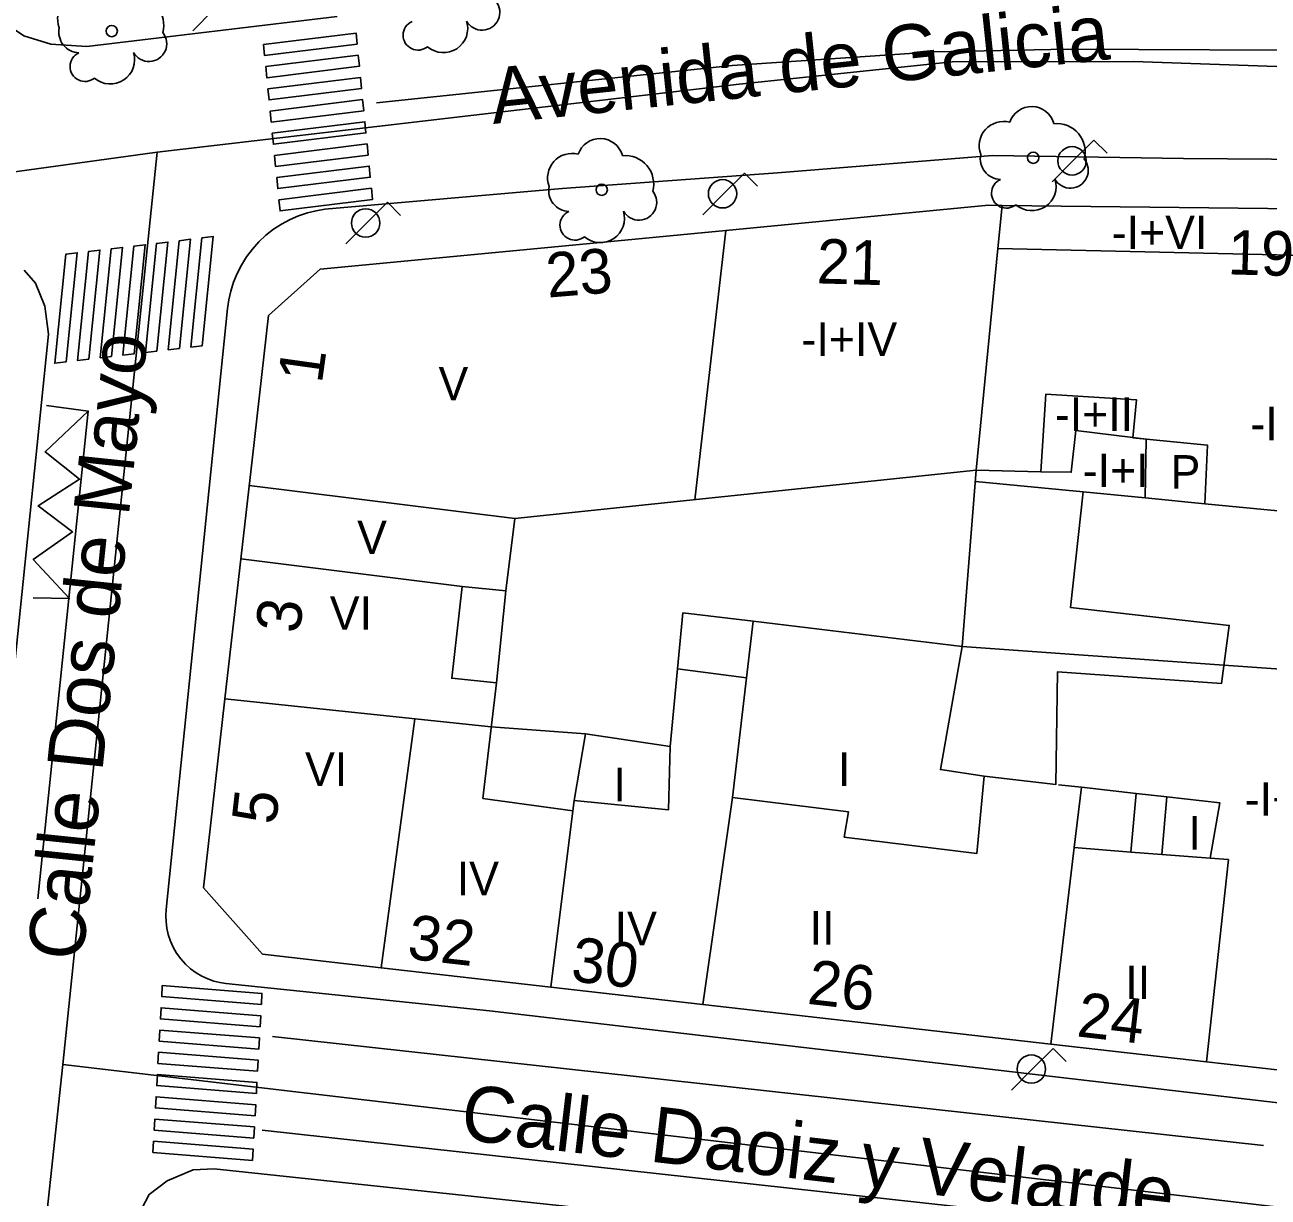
# Model space of a CAD drawing. Extents: x 282771 to 285132, y 4823109 to 4825496.
# Drawn here: x 283049.2 to 283104.9, y 4824300.3 to 4824352.9 of the extents above; entities that cross this region are included whole.
import ezdxf

# ---------------------------------------------------------------- set-up
doc = ezdxf.new("R2010")
doc.units = 0
for name, color, linetype in [('ACERA-BORDILLO', 7, 'Continuous'), ('ARBOL', 7, 'Continuous'), ('CALLE-EJE', 7, 'Continuous'), ('CALLE-TEXTO', 7, 'Continuous'), ('CARGA_DESCARGA', 7, 'Continuous'), ('EDIFICIO', 7, 'Continuous'), ('FAROLA', 7, 'Continuous'), ('INTERIOR-EDIFICIO', 7, 'Continuous'), ('MEDIANERA', 7, 'Continuous'), ('NUM-LOCAL', 7, 'Continuous'), ('NUM-PORTAL', 7, 'Continuous'), ('PASO-PEATONES', 7, 'Continuous'), ('SENAL-VIARIA', 7, 'Continuous'), ('TXT-ALTURA-EDIFICIO', 7, 'Continuous')]:
    doc.layers.add(name, color=color, linetype=linetype)

msp = doc.modelspace()

# ---------------------------------------------------------------- linework, layer by layer
at = {"layer": 'ACERA-BORDILLO'}
for points in [[(283063.163, 4824353.319), (283051.925, 4824351.968), (283050.316, 4824352.068), (283049.108, 4824352.451), (283048.263, 4824353.014)], [(283101.131, 4824346.943), (283092.557, 4824347.075), (283082.908, 4824346.3), (283073.26, 4824345.596), (283062.607, 4824344.665), (283062.217, 4824344.601), (283061.825, 4824344.504), (283061.433, 4824344.373), (283061.046, 4824344.206), (283060.67, 4824344.004), (283060.308, 4824343.768), (283059.966, 4824343.499), (283059.647, 4824343.2), (283059.355, 4824342.875), (283059.094, 4824342.527), (283058.865, 4824342.16), (283058.671, 4824341.78), (283058.513, 4824341.39), (283058.39, 4824340.995), (283058.301, 4824340.601), (283058.245, 4824340.21), (283055.497, 4824313.24), (283055.479, 4824312.969), (283055.486, 4824312.689), (283055.521, 4824312.403), (283055.585, 4824312.114), (283055.679, 4824311.827), (283055.804, 4824311.546), (283055.959, 4824311.277), (283056.142, 4824311.025), (283056.35, 4824310.792), (283056.58, 4824310.584), (283056.828, 4824310.402), (283057.088, 4824310.248), (283057.357, 4824310.124), (283057.629, 4824310.029), (283057.902, 4824309.963), (283058.17, 4824309.923), (283069.988, 4824308.701), (283107.558, 4824304.319)], [(283110.99, 4824346.873), (283101.131, 4824346.943)], [(283049.123, 4824341.934), (283049.628, 4824341.348), (283050.042, 4824340.313), (283050.215, 4824339.059), (283045.739, 4824295.551)], [(283057.649, 4824301.605), (283056.704, 4824301.565), (283055.537, 4824301.062), (283054.732, 4824300.458), (283053.927, 4824298.908)], [(283105.578, 4824296.501), (283057.649, 4824301.605)]]:
    msp.add_lwpolyline(points, dxfattribs=at)
at = {"layer": 'ARBOL'}
for centre in [(283053.048, 4824352.663), (283094.384, 4824346.977), (283075.026, 4824345.543)]:
    msp.add_circle(centre, 0.255, dxfattribs=at)
for centre, radius, start, end in [((283051.718, 4824353.193), 1.097, 75.4318, 200.5561), ((283054.108, 4824352.923), 1.272, 345.0327, 95.7993), ((283069.66, 4824353.498), 0.797, 208.9625, 38.991), ((283066.79, 4824352.478), 0.672, 113.7367, 309.4725), ((283067.93, 4824352.778), 1.086, 228.9545, 17.928), ((283051.608, 4824352.623), 0.935, 168.599, 268.1324), ((283054.718, 4824352.093), 0.797, 208.9625, 38.991), ((283051.848, 4824351.073), 0.672, 113.7367, 309.4725), ((283052.988, 4824351.373), 1.086, 228.9545, 17.928), ((283094.314, 4824348.237), 1.038, 15.6423, 161.3843), ((283093.054, 4824347.507), 1.097, 75.4318, 200.5561), ((283095.444, 4824347.237), 1.272, 345.0327, 95.7993), ((283074.956, 4824346.803), 1.038, 15.6423, 161.3843), ((283073.696, 4824346.073), 1.097, 75.4318, 200.5561), ((283076.086, 4824345.803), 1.272, 345.0327, 95.7992), ((283092.944, 4824346.937), 0.935, 168.599, 268.1324), ((283096.054, 4824346.407), 0.797, 208.9625, 38.991), ((283073.586, 4824345.503), 0.935, 168.599, 268.1324), ((283093.184, 4824345.387), 0.672, 113.7367, 309.4725), ((283094.324, 4824345.687), 1.086, 228.9545, 17.928), ((283076.696, 4824344.973), 0.797, 208.9625, 38.991), ((283073.826, 4824343.953), 0.672, 113.7367, 309.4725), ((283074.966, 4824344.253), 1.086, 228.9545, 17.928)]:
    msp.add_arc(centre, radius, start, end, dxfattribs=at)
at = {"layer": 'CALLE-EJE'}
for points in [[(283119.458, 4824350.58), (283098.878, 4824351.3), (283090.752, 4824351.284), (283081.188, 4824350.281), (283055.088, 4824347.221)], [(283055.088, 4824347.221), (283042.609, 4824345.501)], [(283055.088, 4824347.221), (283050.849, 4824306.281)], [(283045.479, 4824254.042), (283049.709, 4824295.551), (283050.849, 4824306.281)], [(283113.935, 4824298.88), (283050.849, 4824306.281)]]:
    msp.add_lwpolyline(points, dxfattribs=at)
at = {"layer": 'CARGA_DESCARGA'}
msp.add_lwpolyline([(283050.129, 4824335.859), (283051.995, 4824335.612), (283050.059, 4824333.78), (283051.608, 4824332.547), (283049.742, 4824331.35), (283051.291, 4824330.187), (283049.53, 4824328.954), (283051.15, 4824327.193), (283049.53, 4824327.228)], dxfattribs=at)
at = {"layer": 'EDIFICIO'}
msp.add_lwpolyline([(283058.128, 4824322.691), (283059.358, 4824333.541), (283060.078, 4824339.891), (283062.398, 4824341.971), (283072.458, 4824342.931), (283080.598, 4824343.711), (283092.378, 4824344.851), (283092.988, 4824344.841), (283110.208, 4824344.641), (283113.058, 4824341.861), (283111.778, 4824330.521), (283110.988, 4824323.631), (283110.268, 4824317.201), (283109.287, 4824308.473), (283106.126, 4824305.952), (283102.158, 4824306.401), (283095.178, 4824307.201), (283079.558, 4824308.981), (283072.748, 4824309.761), (283065.128, 4824310.631), (283059.808, 4824311.241), (283057.169, 4824314.221), (283058.128, 4824322.691)], dxfattribs=at)
at = {"layer": 'FAROLA'}
for p, q in [((283057.61, 4824353.616), (283056.68, 4824352.676)), ((283097.107, 4824347.769), (283096.167, 4824346.839)), ((283097.697, 4824347.179), (283097.107, 4824347.769)), ((283096.167, 4824346.839), (283095.237, 4824345.899)), ((283081.428, 4824346.29), (283080.488, 4824345.36)), ((283082.018, 4824345.7), (283081.428, 4824346.29)), ((283080.488, 4824345.36), (283079.558, 4824344.42)), ((283065.418, 4824344.978), (283064.478, 4824344.048)), ((283066.008, 4824344.388), (283065.418, 4824344.978)), ((283064.478, 4824344.048), (283063.548, 4824343.108)), ((283095.278, 4824307.011), (283094.338, 4824306.081)), ((283095.868, 4824306.421), (283095.278, 4824307.011)), ((283094.338, 4824306.081), (283093.408, 4824305.141))]:
    msp.add_line(p, q, dxfattribs=at)
for centre in [(283096.127, 4824346.839), (283080.448, 4824345.36), (283064.438, 4824344.048), (283094.298, 4824306.081)]:
    msp.add_circle(centre, 0.637, dxfattribs=at)
at = {"layer": 'INTERIOR-EDIFICIO'}
for points in [[(283091.822, 4824332.951), (283094.728, 4824332.881), (283094.948, 4824336.361), (283099.018, 4824336.111), (283098.847, 4824334.41), (283102.198, 4824334.081), (283102.078, 4824331.451), (283099.408, 4824331.721), (283096.628, 4824331.991), (283096.058, 4824326.791), (283103.178, 4824325.991), (283102.828, 4824323.381), (283095.478, 4824323.911), (283095.405, 4824318.854), (283092.188, 4824319.221), (283091.848, 4824315.751), (283085.908, 4824316.491), (283086.098, 4824317.621), (283080.888, 4824318.271), (283081.518, 4824323.641), (283078.428, 4824324.041), (283078.098, 4824320.551), (283078.018, 4824317.711), (283073.798, 4824318.141), (283073.728, 4824317.671), (283069.699, 4824318.224)], [(283098.848, 4824334.421), (283099.448, 4824334.351)], [(283091.822, 4824332.951), (283071.123, 4824330.783), (283070.722, 4824327.544), (283068.765, 4824327.739), (283068.298, 4824323.621), (283070.312, 4824323.421), (283069.699, 4824318.224)]]:
    msp.add_lwpolyline(points, dxfattribs=at)
at = {"layer": 'MEDIANERA'}
for points in [[(283092.798, 4824342.901), (283092.988, 4824344.841)], [(283079.197, 4824331.629), (283080.598, 4824343.711)], [(283091.828, 4824332.951), (283092.798, 4824342.901)], [(283092.798, 4824342.901), (283110.588, 4824342.501), (283111.118, 4824341.891), (283109.718, 4824330.711)], [(283098.848, 4824334.421), (283096.298, 4824334.731), (283096.088, 4824332.861), (283094.728, 4824332.881)], [(283099.408, 4824331.721), (283099.448, 4824334.351)], [(283091.198, 4824325.041), (283091.822, 4824332.951)], [(283059.214, 4824332.265), (283071.123, 4824330.783)], [(283096.628, 4824331.991), (283091.788, 4824332.451)], [(283109.718, 4824330.711), (283102.078, 4824331.451)], [(283058.841, 4824328.973), (283068.765, 4824327.739)], [(283070.312, 4824323.421), (283070.722, 4824327.544)], [(283078.668, 4824326.561), (283078.428, 4824324.041)], [(283078.668, 4824326.561), (283081.818, 4824326.181)], [(283081.518, 4824323.641), (283081.818, 4824326.181)], [(283081.818, 4824326.181), (283091.198, 4824325.041)], [(283092.188, 4824319.221), (283090.218, 4824319.521), (283091.198, 4824325.041)], [(283110.988, 4824323.631), (283102.938, 4824324.201), (283091.198, 4824325.041)], [(283058.128, 4824322.691), (283070.064, 4824321.444)], [(283066.651, 4824321.801), (283065.128, 4824310.631)], [(283074.298, 4824321.131), (283070.064, 4824321.444)], [(283073.798, 4824318.141), (283074.298, 4824321.131)], [(283078.098, 4824320.551), (283074.298, 4824321.131)], [(283095.518, 4824318.841), (283096.548, 4824318.731)], [(283080.888, 4824318.271), (283079.558, 4824308.981)], [(283096.218, 4824316.021), (283096.548, 4824318.731)], [(283096.548, 4824318.731), (283099.008, 4824318.451)], [(283098.768, 4824315.821), (283099.008, 4824318.451)], [(283099.008, 4824318.451), (283100.378, 4824318.301)], [(283100.148, 4824315.711), (283100.378, 4824318.301)], [(283100.378, 4824318.301), (283102.748, 4824318.031), (283102.328, 4824315.541)], [(283073.728, 4824317.671), (283072.748, 4824309.761)], [(283096.218, 4824316.021), (283095.178, 4824307.201)], [(283098.768, 4824315.821), (283096.218, 4824316.021)], [(283100.148, 4824315.711), (283098.768, 4824315.821)], [(283102.328, 4824315.541), (283100.148, 4824315.711)], [(283102.328, 4824315.541), (283103.138, 4824315.481), (283102.158, 4824306.401)]]:
    msp.add_lwpolyline(points, dxfattribs=at)
at = {"layer": 'PASO-PEATONES'}
for points in [[(283059.857, 4824352.06), (283064.008, 4824352.573), (283064.057, 4824352.076), (283059.906, 4824351.562)], [(283059.956, 4824351.065), (283064.106, 4824351.578), (283064.156, 4824351.08), (283060.005, 4824350.567)], [(283060.054, 4824350.069), (283064.205, 4824350.583), (283064.254, 4824350.085), (283060.103, 4824349.571)], [(283060.152, 4824349.074), (283064.303, 4824349.587), (283064.353, 4824349.09), (283060.202, 4824348.576)], [(283060.251, 4824348.078), (283064.402, 4824348.592), (283064.451, 4824348.094), (283060.3, 4824347.581)], [(283060.349, 4824347.083), (283064.5, 4824347.596), (283064.55, 4824347.099), (283060.399, 4824346.585)], [(283060.448, 4824346.087), (283064.599, 4824346.601), (283064.648, 4824346.103), (283060.497, 4824345.59)], [(283060.547, 4824345.092), (283064.697, 4824345.605), (283064.747, 4824345.108), (283060.596, 4824344.594)], [(283057.107, 4824338.544), (283056.599, 4824338.484), (283057.093, 4824343.377), (283057.602, 4824343.437)], [(283052.021, 4824337.94), (283051.512, 4824337.88), (283052.007, 4824342.773), (283052.516, 4824342.833)], [(283053.038, 4824338.061), (283052.53, 4824338), (283053.024, 4824342.894), (283053.533, 4824342.954)], [(283054.056, 4824338.182), (283053.547, 4824338.121), (283054.042, 4824343.014), (283054.55, 4824343.075)], [(283055.073, 4824338.303), (283054.564, 4824338.242), (283055.059, 4824343.135), (283055.567, 4824343.196)], [(283056.09, 4824338.423), (283055.582, 4824338.363), (283056.076, 4824343.256), (283056.585, 4824343.317)], [(283051.004, 4824337.819), (283050.495, 4824337.759), (283050.99, 4824342.652), (283051.498, 4824342.712)], [(283059.759, 4824308.977), (283055.289, 4824309.332), (283055.317, 4824309.831), (283059.787, 4824309.477)], [(283059.703, 4824307.978), (283055.234, 4824308.333), (283055.262, 4824308.833), (283059.731, 4824308.478)], [(283059.647, 4824306.98), (283055.178, 4824307.335), (283055.206, 4824307.834), (283059.675, 4824307.479)], [(283059.591, 4824305.981), (283055.122, 4824306.336), (283055.15, 4824306.835), (283059.619, 4824306.48)], [(283059.535, 4824304.982), (283055.066, 4824305.337), (283055.094, 4824305.837), (283059.563, 4824305.482)], [(283059.479, 4824303.984), (283055.01, 4824304.339), (283055.038, 4824304.838), (283059.507, 4824304.483)], [(283059.423, 4824302.985), (283054.954, 4824303.34), (283054.982, 4824303.839), (283059.451, 4824303.484)], [(283059.367, 4824301.986), (283054.898, 4824302.341), (283054.926, 4824302.841), (283059.395, 4824302.486)]]:
    msp.add_lwpolyline(points, close=True, dxfattribs=at)
at = {"layer": 'SENAL-VIARIA'}
for points in [[(283064.921, 4824349.448), (283080.881, 4824351.113), (283089.939, 4824351.729), (283095.917, 4824351.853), (283108.672, 4824351.791)], [(283051.995, 4824335.612), (283049.726, 4824313.727)], [(283104.716, 4824302.649), (283060.256, 4824307.542)], [(283104.254, 4824298.45), (283059.794, 4824303.343)]]:
    msp.add_lwpolyline(points, dxfattribs=at)

# ---------------------------------------------------------------- texts
at = {"layer": 'CALLE-TEXTO'}
for s, rotation, p in [('Avenida de Galicia', 5.9927, (283070.156, 4824348.491)), ('Calle Dos de Mayo', 84.0873, (283051.743, 4824310.884)), ('Calle Daoiz y Velarde', 353.3091, (283068.634, 4824302.936))]:
    msp.add_text(s, height=2.5, rotation=rotation, dxfattribs=at).set_placement(p)
at = {"layer": 'NUM-LOCAL'}
msp.add_text('23', height=2, rotation=4.73, dxfattribs=at).set_placement((283072.606, 4824340.699))
at = {"layer": 'NUM-PORTAL'}
for s, rotation, p in [('21', 358.4097, (283084.656, 4824341.342)), ('19', 358.41, (283103.086, 4824341.747)), ('1', 82.0566, (283062.472, 4824336.809)), ('3', 83.53, (283061.482, 4824325.596)), ('5', 83.53, (283060.411, 4824317.011)), ('32', 353.49, (283066.261, 4824311.04)), ('30', 353.49, (283073.602, 4824310.035)), ('26', 353.4898, (283084.207, 4824309.017)), ('24', 353.49, (283096.295, 4824307.553))]:
    msp.add_text(s, height=2, rotation=rotation, dxfattribs=at).set_placement(p)
at = {"layer": 'TXT-ALTURA-EDIFICIO'}
for s, rotation, p in [('-I+VI', 0, (283097.906, 4824342.881)), ('-I+IV', 359.9997, (283083.989, 4824338.088)), ('V', 0, (283067.706, 4824336.093)), ('-I+II', 0, (283095.354, 4824334.721)), ('-I+VII', 0, (283104.126, 4824334.301)), ('-I+I', 0, (283096.605, 4824332.201)), ('P', 0, (283100.543, 4824332.131)), ('V', 0, (283064.055, 4824329.196)), ('VI', 0, (283062.829, 4824325.796)), ('VI', 0, (283061.719, 4824318.791)), ('I', 359.9997, (283085.627, 4824318.791)), ('I', 359.9999, (283075.557, 4824318.101)), ('-I+V', 0, (283103.873, 4824317.448)), ('I', 0, (283101.347, 4824315.931)), ('IV', 359.9999, (283068.524, 4824313.882)), ('IV', 359.9999, (283075.609, 4824311.641)), ('II', 359.9997, (283084.357, 4824311.671)), ('II', 0, (283098.517, 4824309.221))]:
    msp.add_text(s, height=1.5, rotation=rotation, dxfattribs=at).set_placement(p)

doc.saveas('drawing.dxf')
